(* Logix 5000 project; controller Test vendor 1 type 14 code 92 rev 33.11; software revision 33.00; part 2 of 4 *)
(* tags used below, declared in another part *)
   WLS : Banner_WLS_v4;
   Port_Data : Banner_IOL_Port_v4;
   Port : INT;   // Port Number that device is plugged into.
   Type : SINT;   // 0 = WLS27, 1 = WLS15, 2 = WLF
   Local_Control : DINT;
   Command_Being_Processed : BOOL;
   Update_Archive : BOOL;
   Index_Write_Inprocess : DINT;
   Index_Write_Control : DINT;
   IndexR : DINT;   // Index keeping track of Reads in an array.
   S_Index : DINT;
   IndexW : DINT;   // Index keeping track of Writes in an array.
(* Banner_WLS_Param_v4, continued *)

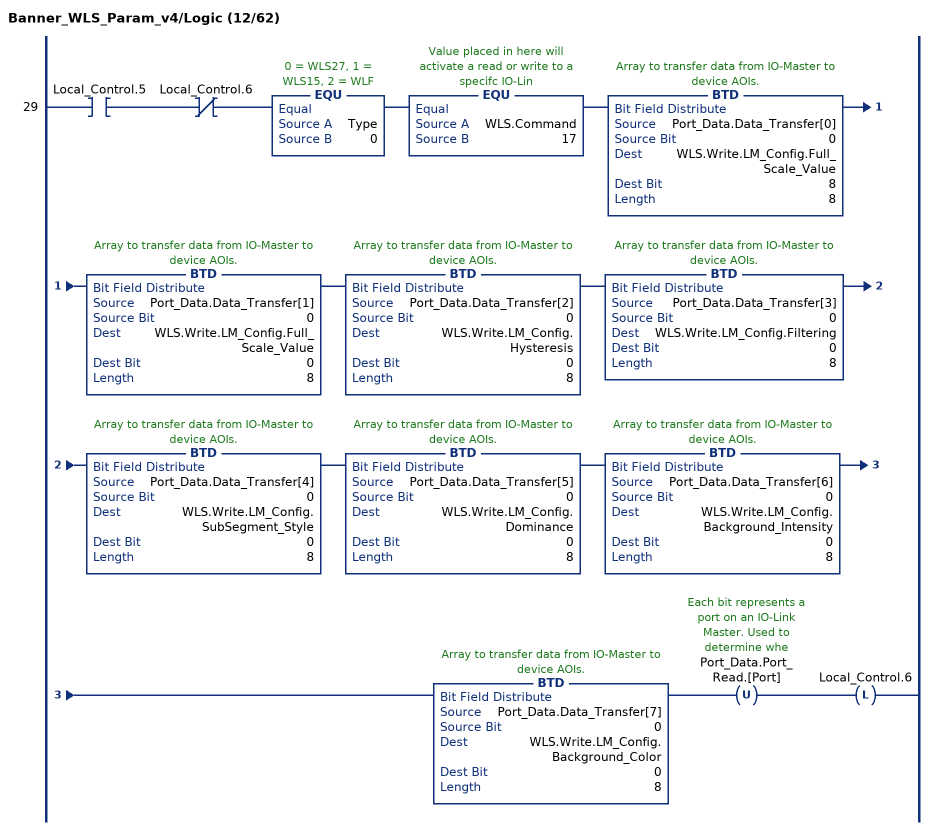
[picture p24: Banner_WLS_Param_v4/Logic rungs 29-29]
   29: XIC(Local_Control.5)XIO(Local_Control.6)EQU(Type,0)EQU(WLS.Command,17)BTD(Port_Data.Data_Transfer[0],0,WLS.Write.LM_Config.Full_Scale_Value,8,8)BTD(Port_Data.Data_Transfer[1],0,WLS.Write.LM_Config.Full_Scale_Value,0,8)BTD(Port_Data.Data_Transfer[2],0,WLS.Write.LM_Config.Hysteresis,0,8)BTD(Port_Data.Data_Transfer[3],0,WLS.Write.LM_Config.Filtering,0,8)BTD(Port_Data.Data_Transfer[4],0,WLS.Write.LM_Config.SubSegment_Style,0,8)BTD(Port_Data.Data_Transfer[5],0,WLS.Write.LM_Config.Dominance,0,8)BTD(Port_Data.Data_Transfer[6],0,WLS.Write.LM_Config.Background_Intensity,0,8)BTD(Port_Data.Data_Transfer[7],0,WLS.Write.LM_Config.Background_Color,0,8)OTU(Port_Data.Port_Read.[Port])OTL(Local_Control.6);
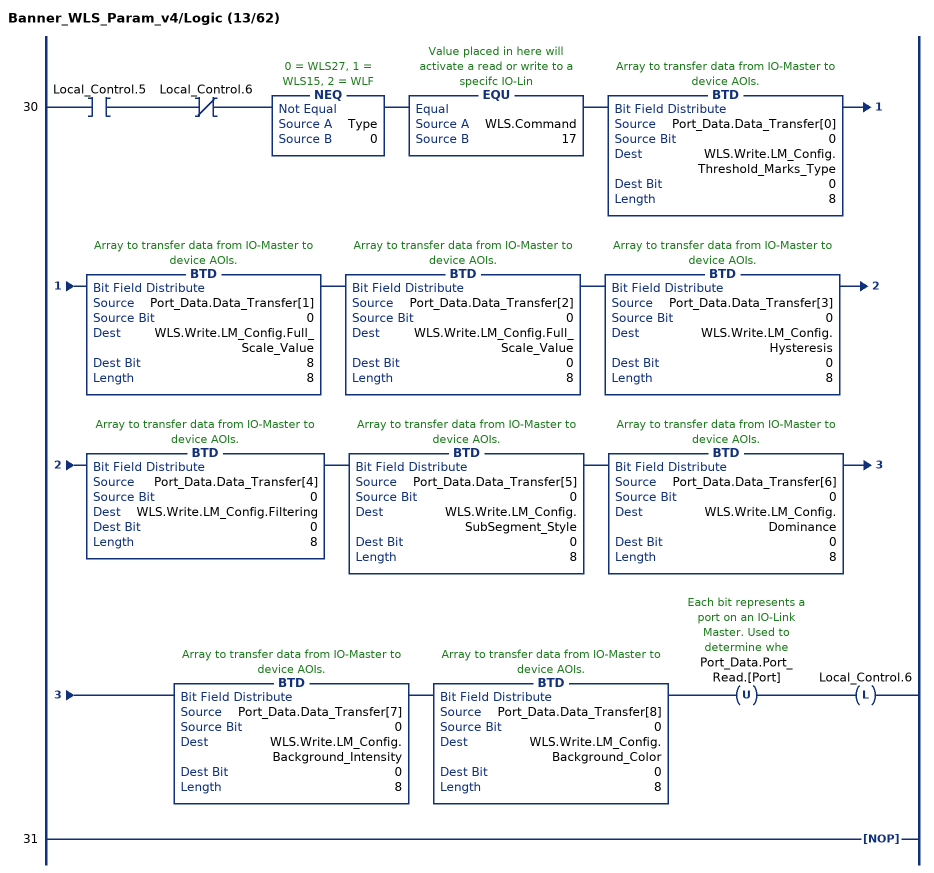
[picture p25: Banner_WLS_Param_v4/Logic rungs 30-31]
   30: XIC(Local_Control.5)XIO(Local_Control.6)NEQ(Type,0)EQU(WLS.Command,17)BTD(Port_Data.Data_Transfer[0],0,WLS.Write.LM_Config.Threshold_Marks_Type,0,8)BTD(Port_Data.Data_Transfer[1],0,WLS.Write.LM_Config.Full_Scale_Value,8,8)BTD(Port_Data.Data_Transfer[2],0,WLS.Write.LM_Config.Full_Scale_Value,0,8)BTD(Port_Data.Data_Transfer[3],0,WLS.Write.LM_Config.Hysteresis,0,8)BTD(Port_Data.Data_Transfer[4],0,WLS.Write.LM_Config.Filtering,0,8)BTD(Port_Data.Data_Transfer[5],0,WLS.Write.LM_Config.SubSegment_Style,0,8)BTD(Port_Data.Data_Transfer[6],0,WLS.Write.LM_Config.Dominance,0,8)BTD(Port_Data.Data_Transfer[7],0,WLS.Write.LM_Config.Background_Intensity,0,8)BTD(Port_Data.Data_Transfer[8],0,WLS.Write.LM_Config.Background_Color,0,8)OTU(Port_Data.Port_Read.[Port])OTL(Local_Control.6);
   31: NOP();
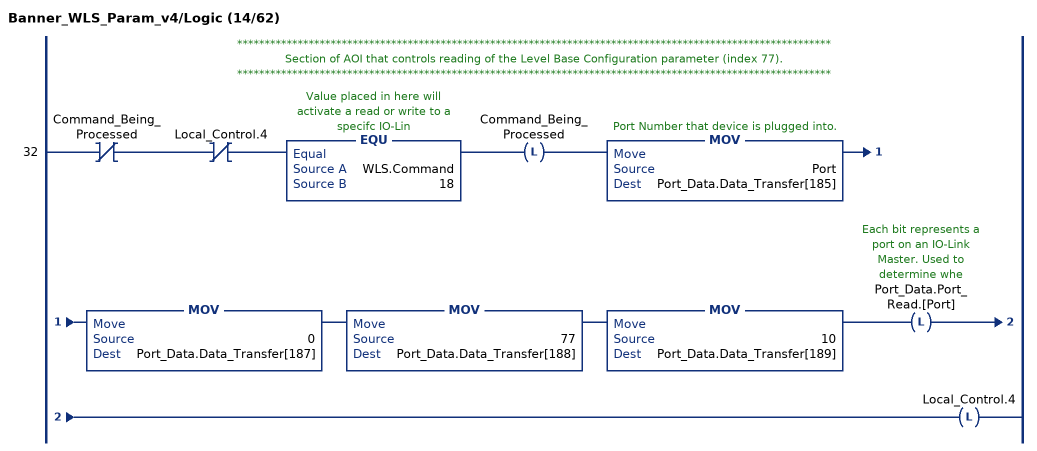
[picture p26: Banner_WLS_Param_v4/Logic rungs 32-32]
   // ************************************************************************************************************
   // Section of AOI that controls reading of the Level Base Configuration parameter (index 77).
   // ************************************************************************************************************
   32: XIO(Command_Being_Processed)XIO(Local_Control.4)EQU(WLS.Command,18)OTL(Command_Being_Processed)MOV(Port,Port_Data.Data_Transfer[185])MOV(0,Port_Data.Data_Transfer[187])MOV(77,Port_Data.Data_Transfer[188])MOV(10,Port_Data.Data_Transfer[189])OTL(Port_Data.Port_Read.[Port])OTL(Local_Control.4);
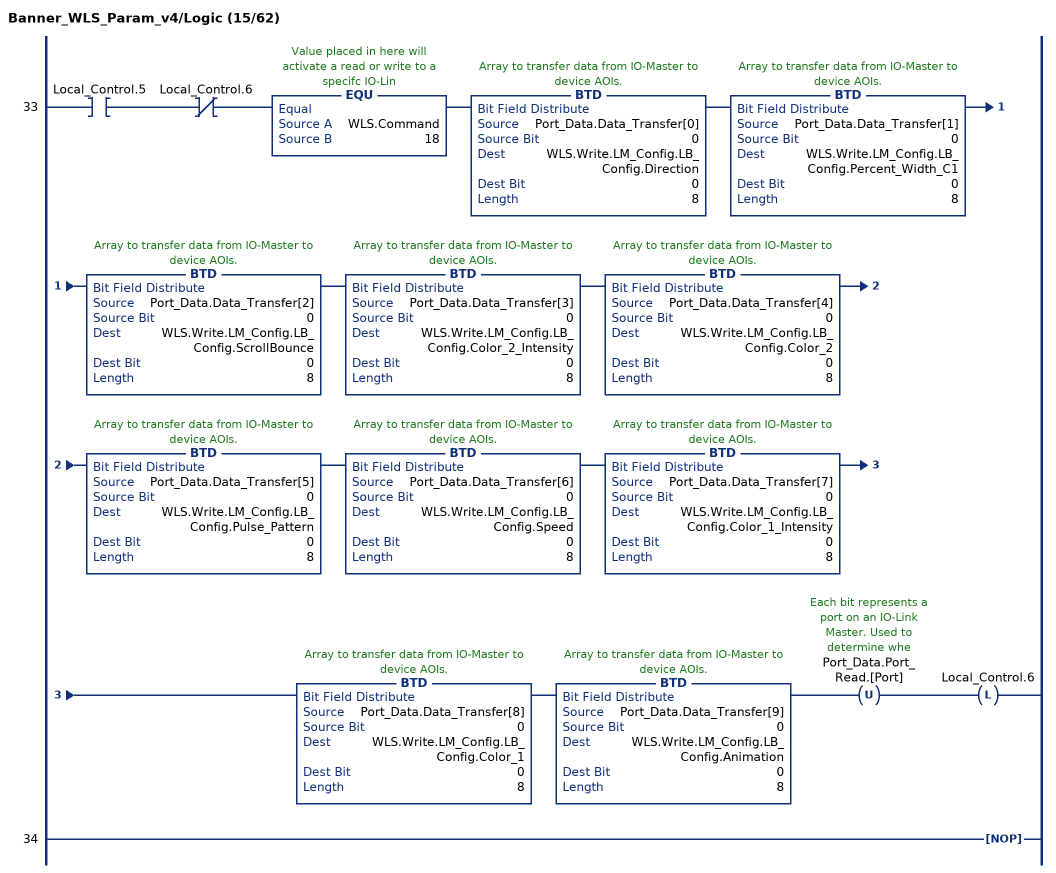
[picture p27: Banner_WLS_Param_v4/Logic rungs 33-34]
   33: XIC(Local_Control.5)XIO(Local_Control.6)EQU(WLS.Command,18)BTD(Port_Data.Data_Transfer[0],0,WLS.Write.LM_Config.LB_Config.Direction,0,8)BTD(Port_Data.Data_Transfer[1],0,WLS.Write.LM_Config.LB_Config.Percent_Width_C1,0,8)BTD(Port_Data.Data_Transfer[2],0,WLS.Write.LM_Config.LB_Config.ScrollBounce,0,8)BTD(Port_Data.Data_Transfer[3],0,WLS.Write.LM_Config.LB_Config.Color_2_Intensity,0,8)BTD(Port_Data.Data_Transfer[4],0,WLS.Write.LM_Config.LB_Config.Color_2,0,8)BTD(Port_Data.Data_Transfer[5],0,WLS.Write.LM_Config.LB_Config.Pulse_Pattern,0,8)BTD(Port_Data.Data_Transfer[6],0,WLS.Write.LM_Config.LB_Config.Speed,0,8)BTD(Port_Data.Data_Transfer[7],0,WLS.Write.LM_Config.LB_Config.Color_1_Intensity,0,8)BTD(Port_Data.Data_Transfer[8],0,WLS.Write.LM_Config.LB_Config.Color_1,0,8)BTD(Port_Data.Data_Transfer[9],0,WLS.Write.LM_Config.LB_Config.Animation,0,8)OTU(Port_Data.Port_Read.[Port])OTL(Local_Control.6);
   34: NOP();
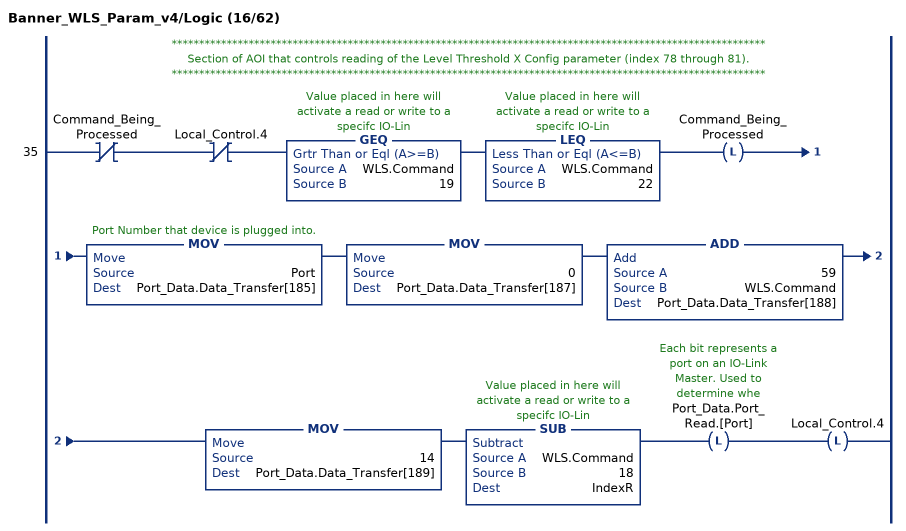
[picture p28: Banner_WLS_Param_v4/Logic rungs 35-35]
   // ************************************************************************************************************
   // Section of AOI that controls reading of the Level Threshold X Config parameter (index 78 through 81).
   // ************************************************************************************************************
   35: XIO(Command_Being_Processed)XIO(Local_Control.4)GEQ(WLS.Command,19)LEQ(WLS.Command,22)OTL(Command_Being_Processed)MOV(Port,Port_Data.Data_Transfer[185])MOV(0,Port_Data.Data_Transfer[187])ADD(59,WLS.Command,Port_Data.Data_Transfer[188])MOV(14,Port_Data.Data_Transfer[189])SUB(WLS.Command,18,IndexR)OTL(Port_Data.Port_Read.[Port])OTL(Local_Control.4);
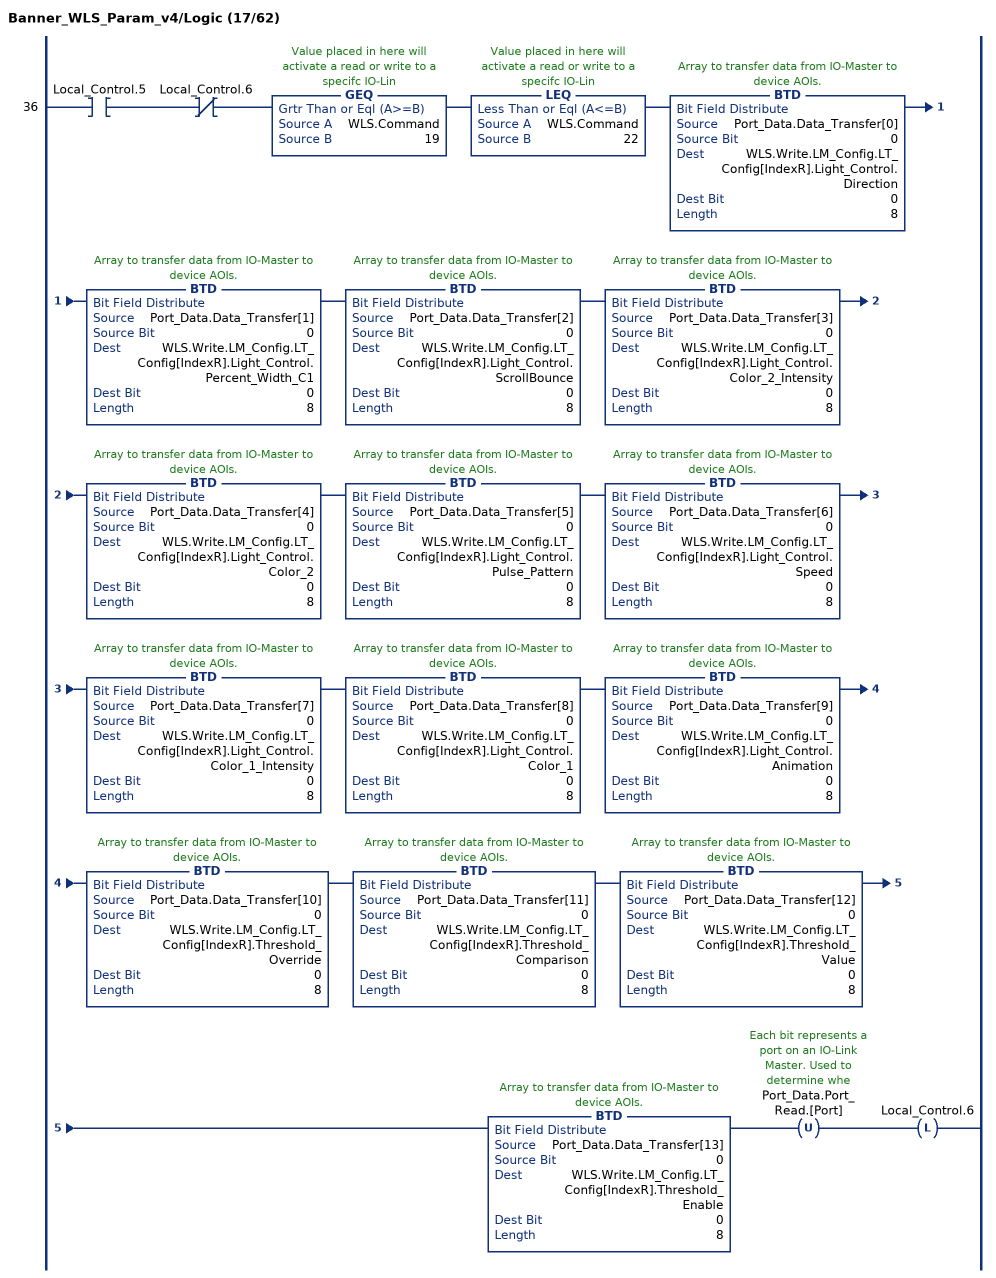
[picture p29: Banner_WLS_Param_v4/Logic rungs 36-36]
   36: XIC(Local_Control.5)XIO(Local_Control.6)GEQ(WLS.Command,19)LEQ(WLS.Command,22)BTD(Port_Data.Data_Transfer[0],0,WLS.Write.LM_Config.LT_Config[IndexR].Light_Control.Direction,0,8)BTD(Port_Data.Data_Transfer[1],0,WLS.Write.LM_Config.LT_Config[IndexR].Light_Control.Percent_Width_C1,0,8)BTD(Port_Data.Data_Transfer[2],0,WLS.Write.LM_Config.LT_Config[IndexR].Light_Control.ScrollBounce,0,8)BTD(Port_Data.Data_Transfer[3],0,WLS.Write.LM_Config.LT_Config[IndexR].Light_Control.Color_2_Intensity,0,8)BTD(Port_Data.Data_Transfer[4],0,WLS.Write.LM_Config.LT_Config[IndexR].Light_Control.Color_2,0,8)BTD(Port_Data.Data_Transfer[5],0,WLS.Write.LM_Config.LT_Config[IndexR].Light_Control.Pulse_Pattern,0,8)BTD(Port_Data.Data_Transfer[6],0,WLS.Write.LM_Config.LT_Config[IndexR].Light_Control.Speed,0,8)BTD(Port_Data.Data_Transfer[7],0,WLS.Write.LM_Config.LT_Config[IndexR].Light_Control.Color_1_Intensity,0,8)BTD(Port_Data.Data_Transfer[8],0,WLS.Write.LM_Config.LT_Config[IndexR].Light_Control.Color_1,0,8)BTD(Port_Data.Data_Transfer[9],0,WLS.Write.LM_Config.LT_Config[IndexR].Light_Control.Animation,0,8)BTD(Port_Data.Data_Transfer[10],0,WLS.Write.LM_Config.LT_Config[IndexR].Threshold_Override,0,8)BTD(Port_Data.Data_Transfer[11],0,WLS.Write.LM_Config.LT_Config[IndexR].Threshold_Comparison,0,8)BTD(Port_Data.Data_Transfer[12],0,WLS.Write.LM_Config.LT_Config[IndexR].Threshold_Value,0,8)BTD(Port_Data.Data_Transfer[13],0,WLS.Write.LM_Config.LT_Config[IndexR].Threshold_Enable,0,8)OTU(Port_Data.Port_Read.[Port])OTL(Local_Control.6);
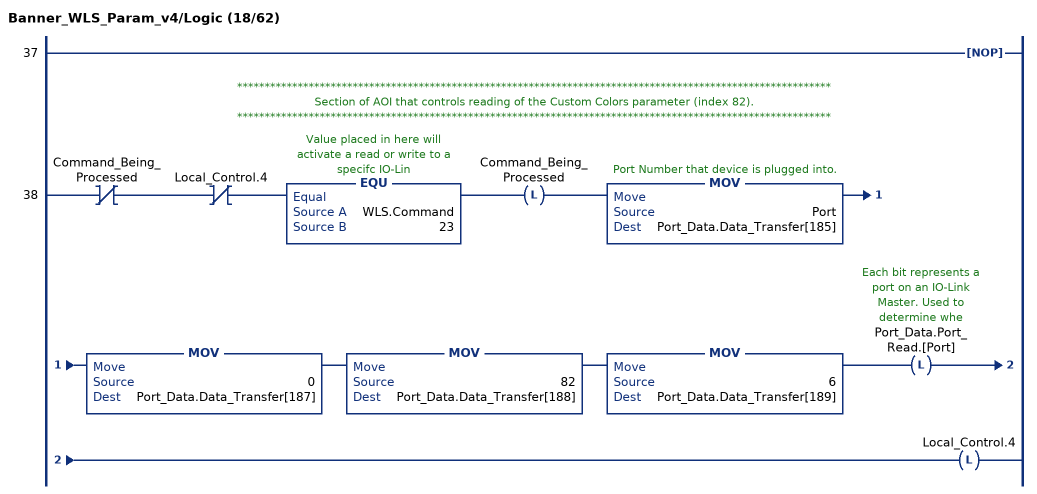
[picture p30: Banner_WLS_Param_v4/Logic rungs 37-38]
   37: NOP();
   // ************************************************************************************************************
   // Section of AOI that controls reading of the Custom Colors parameter (index 82).
   // ************************************************************************************************************
   38: XIO(Command_Being_Processed)XIO(Local_Control.4)EQU(WLS.Command,23)OTL(Command_Being_Processed)MOV(Port,Port_Data.Data_Transfer[185])MOV(0,Port_Data.Data_Transfer[187])MOV(82,Port_Data.Data_Transfer[188])MOV(6,Port_Data.Data_Transfer[189])OTL(Port_Data.Port_Read.[Port])OTL(Local_Control.4);
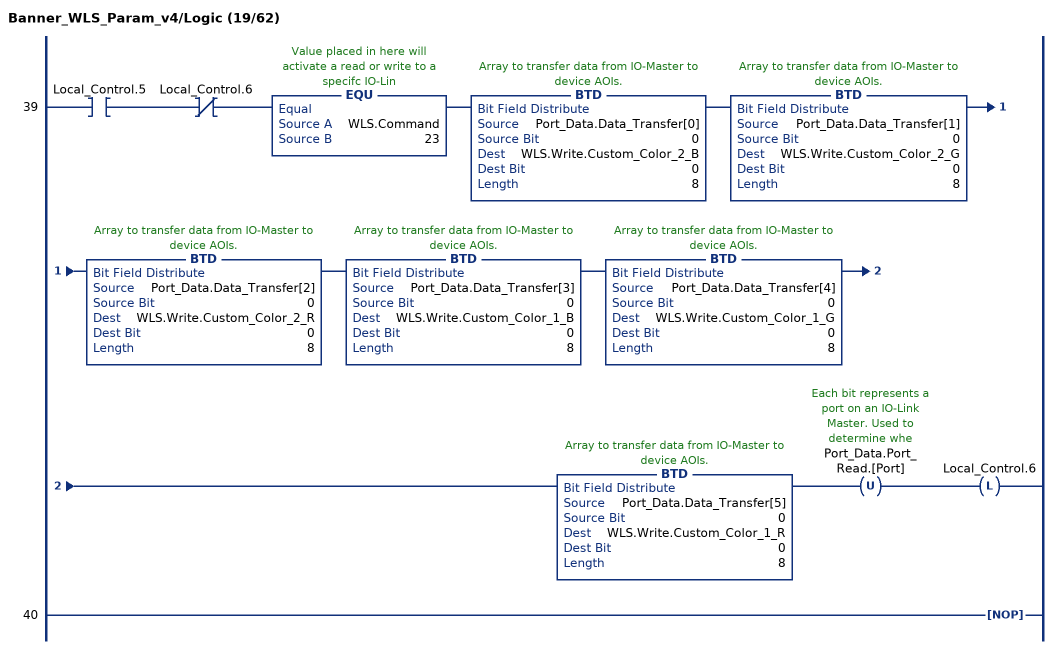
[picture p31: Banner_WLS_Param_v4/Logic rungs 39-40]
   39: XIC(Local_Control.5)XIO(Local_Control.6)EQU(WLS.Command,23)BTD(Port_Data.Data_Transfer[0],0,WLS.Write.Custom_Color_2_B,0,8)BTD(Port_Data.Data_Transfer[1],0,WLS.Write.Custom_Color_2_G,0,8)BTD(Port_Data.Data_Transfer[2],0,WLS.Write.Custom_Color_2_R,0,8)BTD(Port_Data.Data_Transfer[3],0,WLS.Write.Custom_Color_1_B,0,8)BTD(Port_Data.Data_Transfer[4],0,WLS.Write.Custom_Color_1_G,0,8)BTD(Port_Data.Data_Transfer[5],0,WLS.Write.Custom_Color_1_R,0,8)OTU(Port_Data.Port_Read.[Port])OTL(Local_Control.6);
   40: NOP();
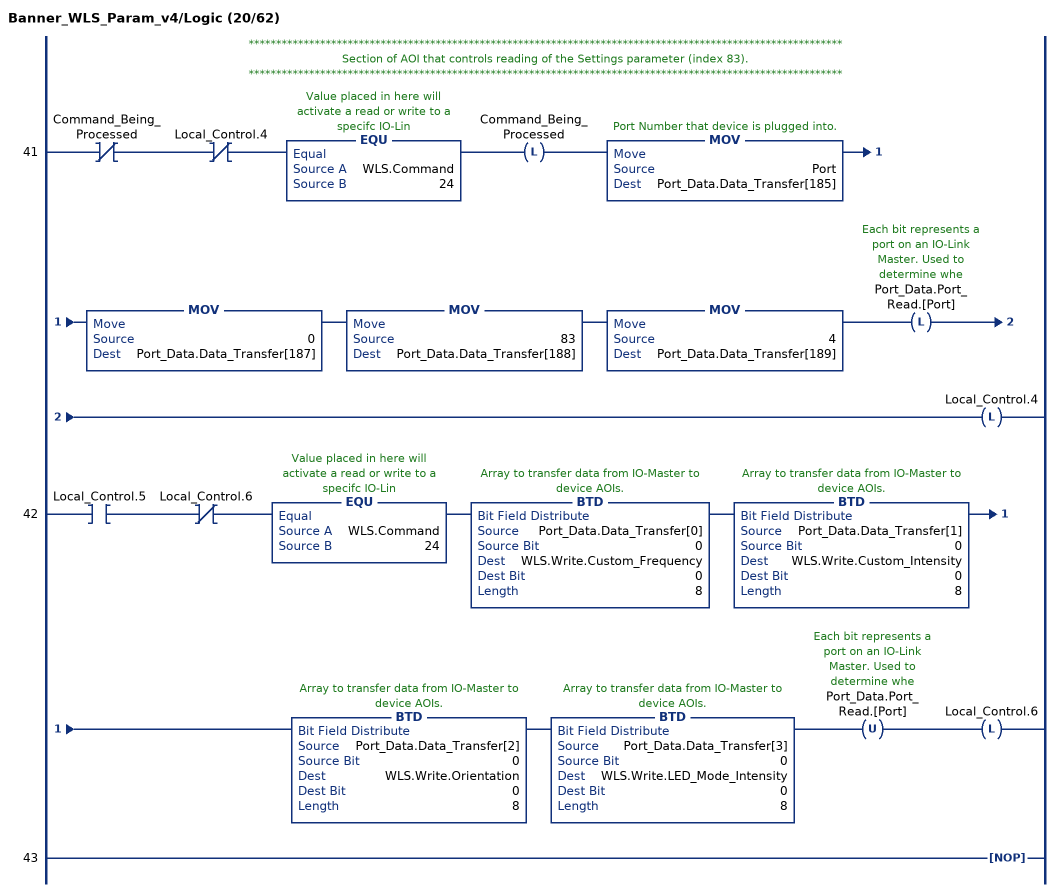
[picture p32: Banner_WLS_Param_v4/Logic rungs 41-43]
   // ************************************************************************************************************
   // Section of AOI that controls reading of the Settings parameter (index 83).
   // ************************************************************************************************************
   41: XIO(Command_Being_Processed)XIO(Local_Control.4)EQU(WLS.Command,24)OTL(Command_Being_Processed)MOV(Port,Port_Data.Data_Transfer[185])MOV(0,Port_Data.Data_Transfer[187])MOV(83,Port_Data.Data_Transfer[188])MOV(4,Port_Data.Data_Transfer[189])OTL(Port_Data.Port_Read.[Port])OTL(Local_Control.4);
   42: XIC(Local_Control.5)XIO(Local_Control.6)EQU(WLS.Command,24)BTD(Port_Data.Data_Transfer[0],0,WLS.Write.Custom_Frequency,0,8)BTD(Port_Data.Data_Transfer[1],0,WLS.Write.Custom_Intensity,0,8)BTD(Port_Data.Data_Transfer[2],0,WLS.Write.Orientation,0,8)BTD(Port_Data.Data_Transfer[3],0,WLS.Write.LED_Mode_Intensity,0,8)OTU(Port_Data.Port_Read.[Port])OTL(Local_Control.6);
   43: NOP();
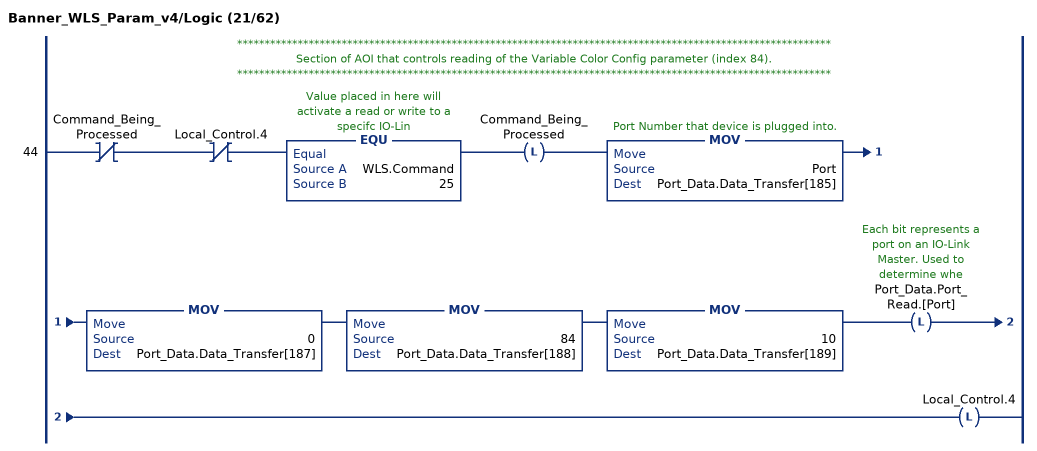
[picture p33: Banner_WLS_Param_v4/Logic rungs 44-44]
   // ************************************************************************************************************
   // Section of AOI that controls reading of the Variable Color Config parameter (index 84).
   // ************************************************************************************************************
   44: XIO(Command_Being_Processed)XIO(Local_Control.4)EQU(WLS.Command,25)OTL(Command_Being_Processed)MOV(Port,Port_Data.Data_Transfer[185])MOV(0,Port_Data.Data_Transfer[187])MOV(84,Port_Data.Data_Transfer[188])MOV(10,Port_Data.Data_Transfer[189])OTL(Port_Data.Port_Read.[Port])OTL(Local_Control.4);
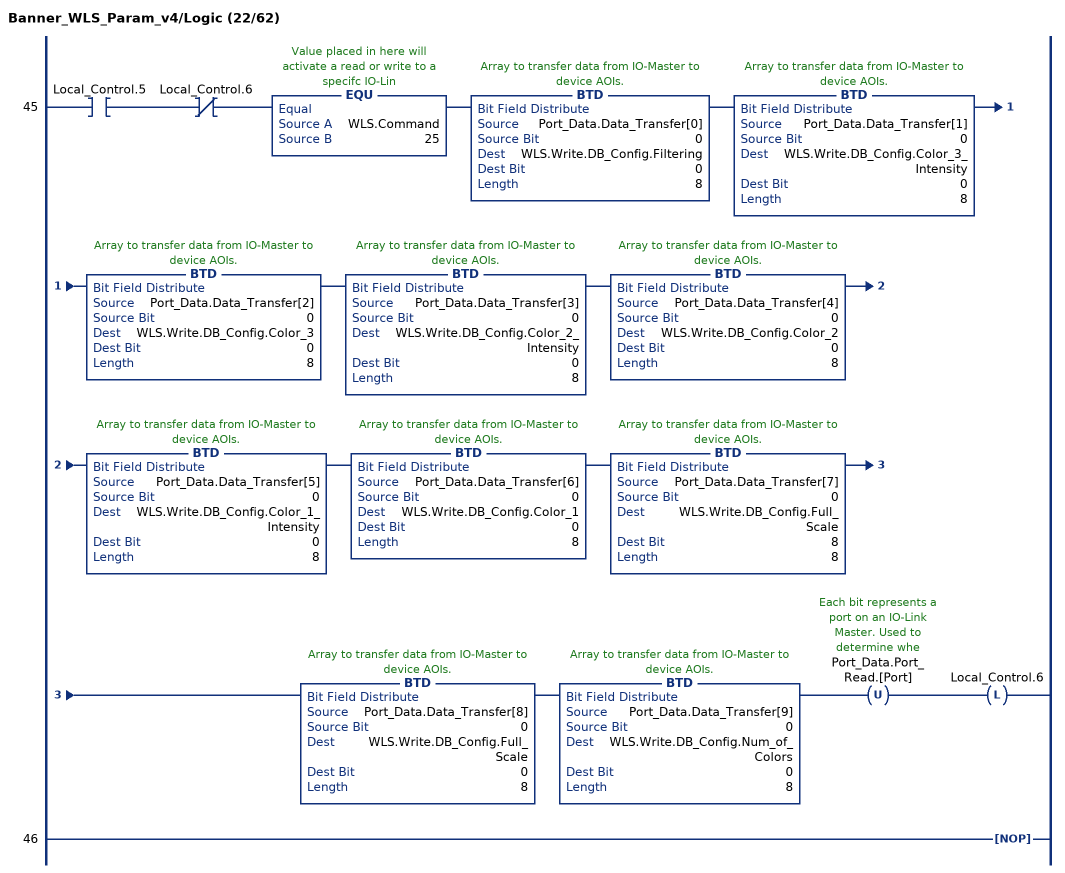
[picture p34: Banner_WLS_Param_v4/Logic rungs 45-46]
   45: XIC(Local_Control.5)XIO(Local_Control.6)EQU(WLS.Command,25)BTD(Port_Data.Data_Transfer[0],0,WLS.Write.DB_Config.Filtering,0,8)BTD(Port_Data.Data_Transfer[1],0,WLS.Write.DB_Config.Color_3_Intensity,0,8)BTD(Port_Data.Data_Transfer[2],0,WLS.Write.DB_Config.Color_3,0,8)BTD(Port_Data.Data_Transfer[3],0,WLS.Write.DB_Config.Color_2_Intensity,0,8)BTD(Port_Data.Data_Transfer[4],0,WLS.Write.DB_Config.Color_2,0,8)BTD(Port_Data.Data_Transfer[5],0,WLS.Write.DB_Config.Color_1_Intensity,0,8)BTD(Port_Data.Data_Transfer[6],0,WLS.Write.DB_Config.Color_1,0,8)BTD(Port_Data.Data_Transfer[7],0,WLS.Write.DB_Config.Full_Scale,8,8)BTD(Port_Data.Data_Transfer[8],0,WLS.Write.DB_Config.Full_Scale,0,8)BTD(Port_Data.Data_Transfer[9],0,WLS.Write.DB_Config.Num_of_Colors,0,8)OTU(Port_Data.Port_Read.[Port])OTL(Local_Control.6);
   46: NOP();
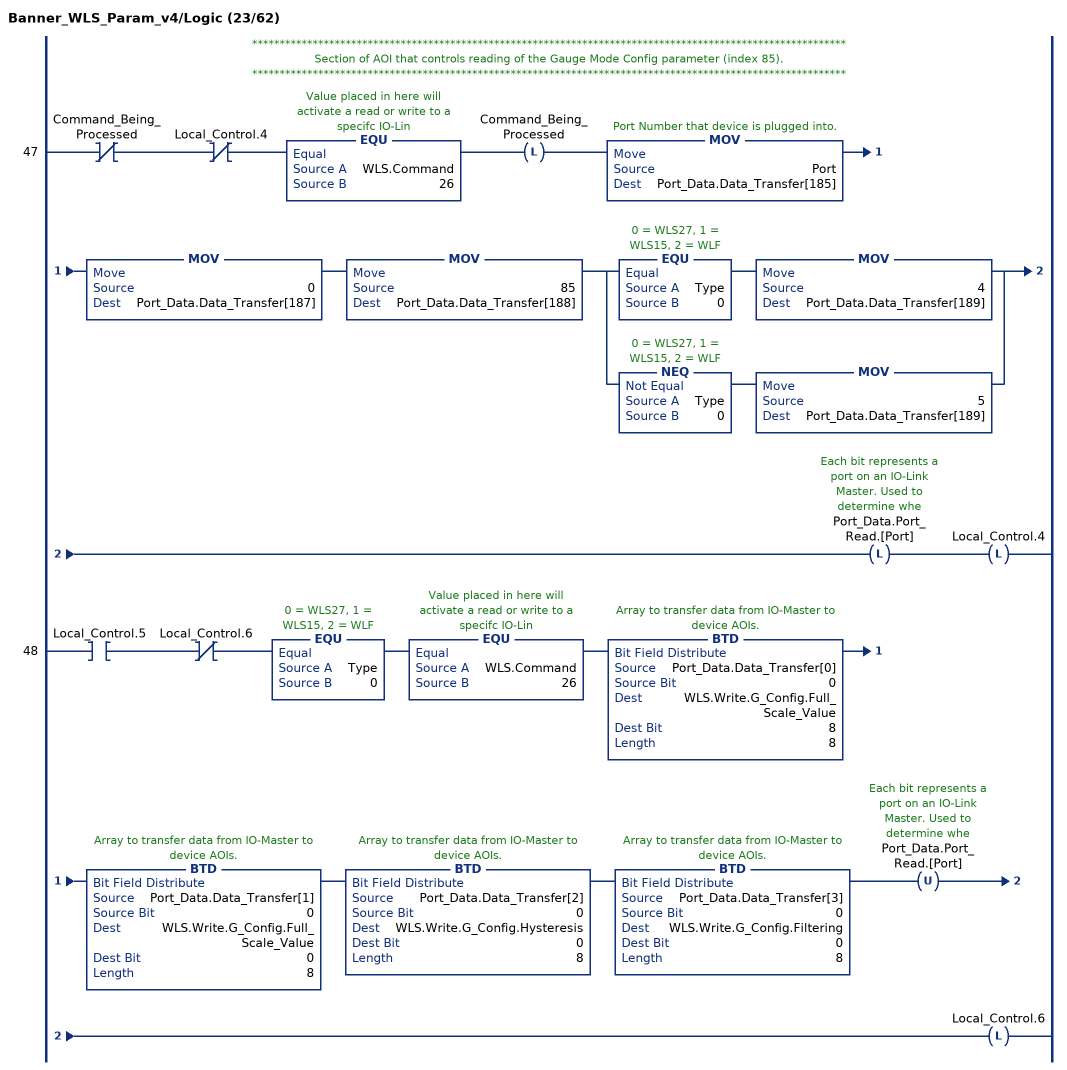
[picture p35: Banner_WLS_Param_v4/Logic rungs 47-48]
   // ************************************************************************************************************
   // Section of AOI that controls reading of the Gauge Mode Config parameter (index 85).
   // ************************************************************************************************************
   47: XIO(Command_Being_Processed)XIO(Local_Control.4)EQU(WLS.Command,26)OTL(Command_Being_Processed)MOV(Port,Port_Data.Data_Transfer[185])MOV(0,Port_Data.Data_Transfer[187])MOV(85,Port_Data.Data_Transfer[188])[EQU(Type,0) MOV(4,Port_Data.Data_Transfer[189]) ,NEQ(Type,0) MOV(5,Port_Data.Data_Transfer[189]) ]OTL(Port_Data.Port_Read.[Port])OTL(Local_Control.4);
   48: XIC(Local_Control.5)XIO(Local_Control.6)EQU(Type,0)EQU(WLS.Command,26)BTD(Port_Data.Data_Transfer[0],0,WLS.Write.G_Config.Full_Scale_Value,8,8)BTD(Port_Data.Data_Transfer[1],0,WLS.Write.G_Config.Full_Scale_Value,0,8)BTD(Port_Data.Data_Transfer[2],0,WLS.Write.G_Config.Hysteresis,0,8)BTD(Port_Data.Data_Transfer[3],0,WLS.Write.G_Config.Filtering,0,8)OTU(Port_Data.Port_Read.[Port])OTL(Local_Control.6);
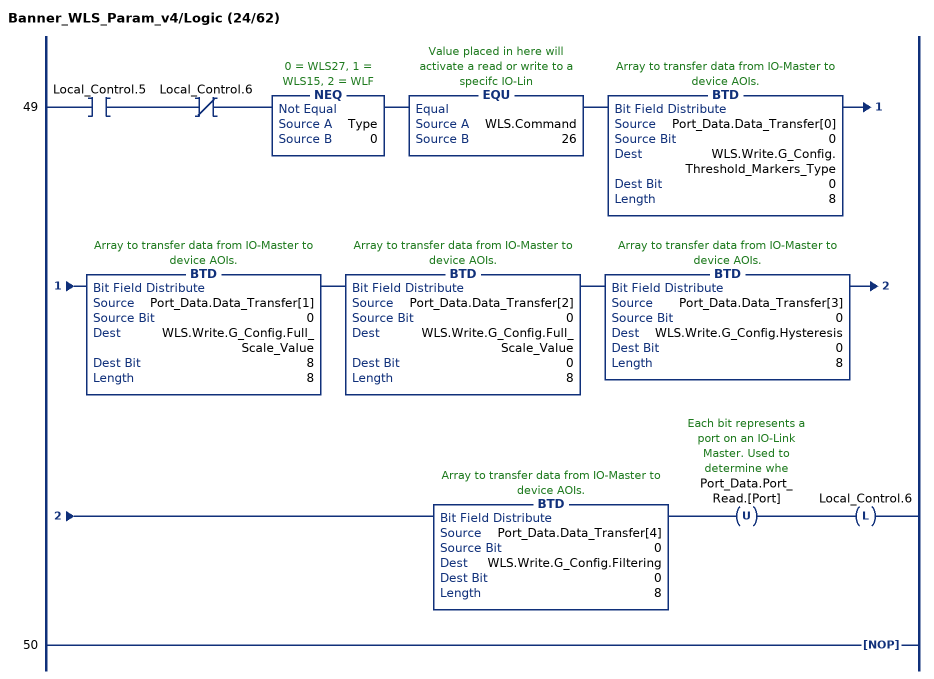
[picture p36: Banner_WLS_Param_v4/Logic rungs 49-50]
   49: XIC(Local_Control.5)XIO(Local_Control.6)NEQ(Type,0)EQU(WLS.Command,26)BTD(Port_Data.Data_Transfer[0],0,WLS.Write.G_Config.Threshold_Markers_Type,0,8)BTD(Port_Data.Data_Transfer[1],0,WLS.Write.G_Config.Full_Scale_Value,8,8)BTD(Port_Data.Data_Transfer[2],0,WLS.Write.G_Config.Full_Scale_Value,0,8)BTD(Port_Data.Data_Transfer[3],0,WLS.Write.G_Config.Hysteresis,0,8)BTD(Port_Data.Data_Transfer[4],0,WLS.Write.G_Config.Filtering,0,8)OTU(Port_Data.Port_Read.[Port])OTL(Local_Control.6);
   50: NOP();
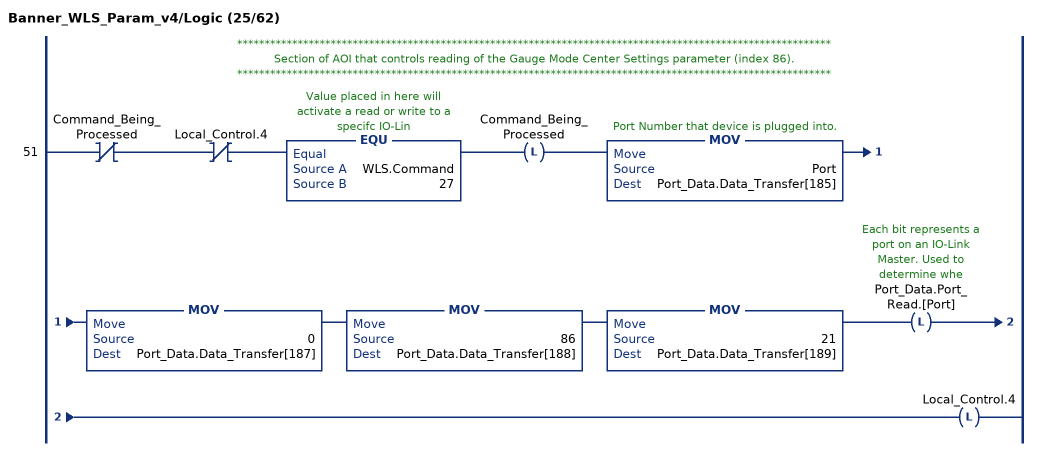
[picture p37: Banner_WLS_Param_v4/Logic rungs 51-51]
   // ************************************************************************************************************
   // Section of AOI that controls reading of the Gauge Mode Center Settings parameter (index 86).
   // ************************************************************************************************************
   51: XIO(Command_Being_Processed)XIO(Local_Control.4)EQU(WLS.Command,27)OTL(Command_Being_Processed)MOV(Port,Port_Data.Data_Transfer[185])MOV(0,Port_Data.Data_Transfer[187])MOV(86,Port_Data.Data_Transfer[188])MOV(21,Port_Data.Data_Transfer[189])OTL(Port_Data.Port_Read.[Port])OTL(Local_Control.4);
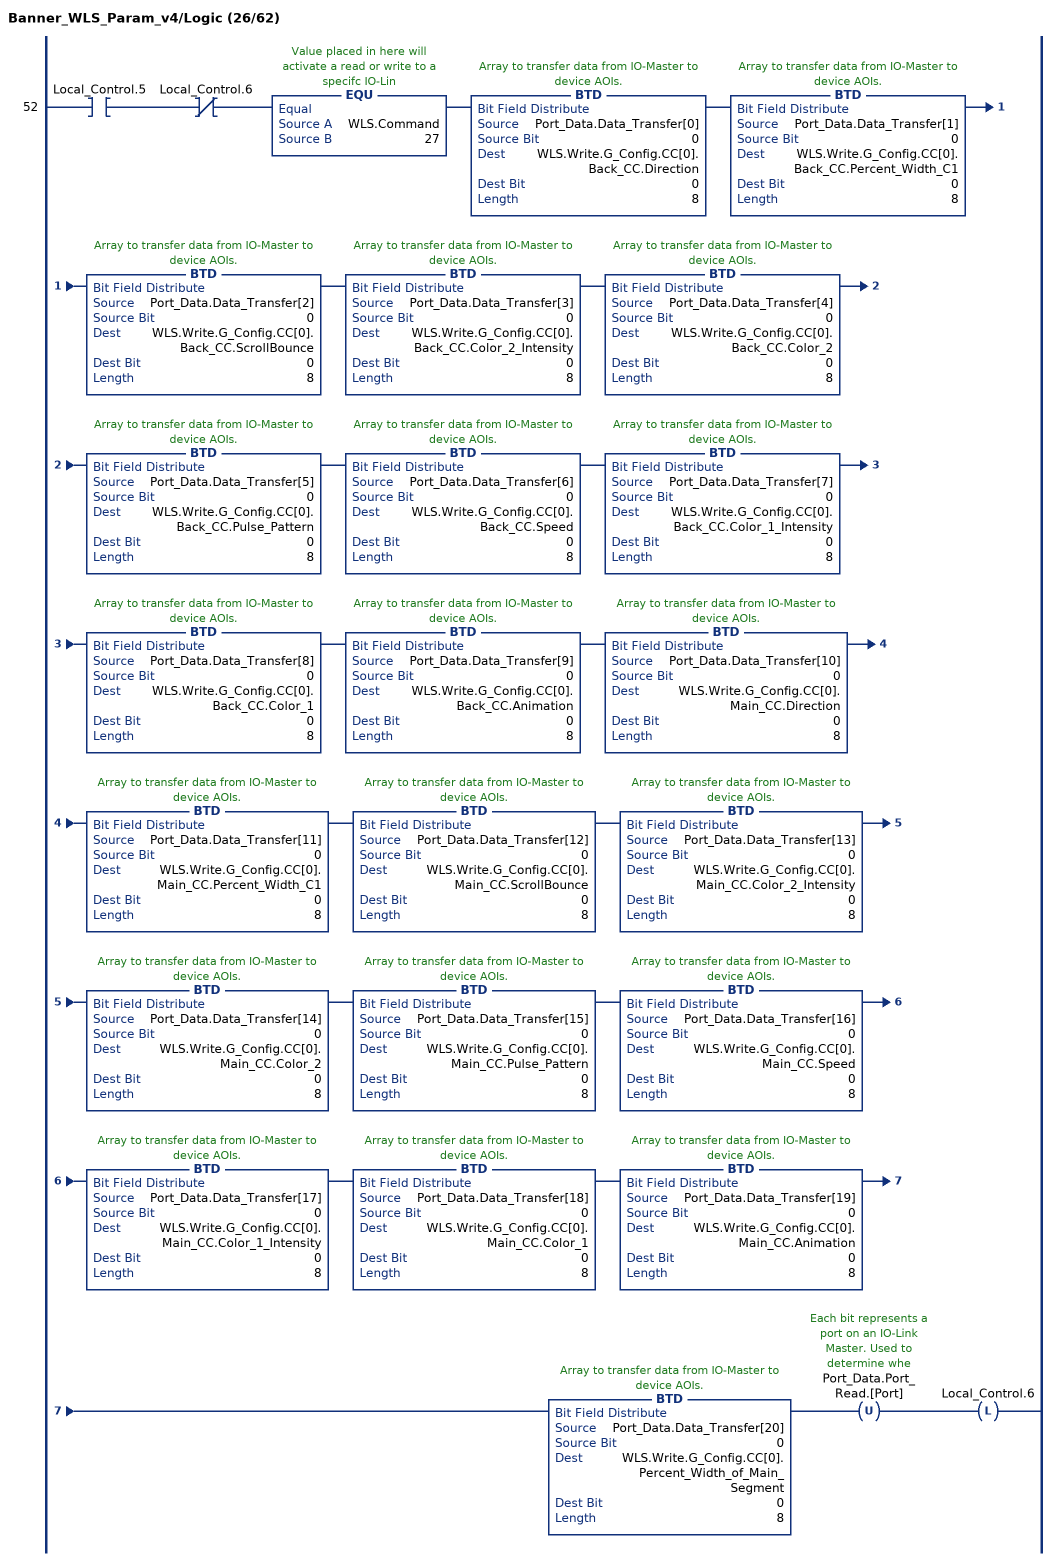
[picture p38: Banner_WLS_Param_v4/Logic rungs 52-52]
   52: XIC(Local_Control.5)XIO(Local_Control.6)EQU(WLS.Command,27)BTD(Port_Data.Data_Transfer[0],0,WLS.Write.G_Config.CC[0].Back_CC.Direction,0,8)BTD(Port_Data.Data_Transfer[1],0,WLS.Write.G_Config.CC[0].Back_CC.Percent_Width_C1,0,8)BTD(Port_Data.Data_Transfer[2],0,WLS.Write.G_Config.CC[0].Back_CC.ScrollBounce,0,8)BTD(Port_Data.Data_Transfer[3],0,WLS.Write.G_Config.CC[0].Back_CC.Color_2_Intensity,0,8)BTD(Port_Data.Data_Transfer[4],0,WLS.Write.G_Config.CC[0].Back_CC.Color_2,0,8)BTD(Port_Data.Data_Transfer[5],0,WLS.Write.G_Config.CC[0].Back_CC.Pulse_Pattern,0,8)BTD(Port_Data.Data_Transfer[6],0,WLS.Write.G_Config.CC[0].Back_CC.Speed,0,8)BTD(Port_Data.Data_Transfer[7],0,WLS.Write.G_Config.CC[0].Back_CC.Color_1_Intensity,0,8)BTD(Port_Data.Data_Transfer[8],0,WLS.Write.G_Config.CC[0].Back_CC.Color_1,0,8)BTD(Port_Data.Data_Transfer[9],0,WLS.Write.G_Config.CC[0].Back_CC.Animation,0,8)BTD(Port_Data.Data_Transfer[10],0,WLS.Write.G_Config.CC[0].Main_CC.Direction,0,8)BTD(Port_Data.Data_Transfer[11],0,WLS.Write.G_Config.CC[0].Main_CC.Percent_Width_C1,0,8)BTD(Port_Data.Data_Transfer[12],0,WLS.Write.G_Config.CC[0].Main_CC.ScrollBounce,0,8)BTD(Port_Data.Data_Transfer[13],0,WLS.Write.G_Config.CC[0].Main_CC.Color_2_Intensity,0,8)BTD(Port_Data.Data_Transfer[14],0,WLS.Write.G_Config.CC[0].Main_CC.Color_2,0,8)BTD(Port_Data.Data_Transfer[15],0,WLS.Write.G_Config.CC[0].Main_CC.Pulse_Pattern,0,8)BTD(Port_Data.Data_Transfer[16],0,WLS.Write.G_Config.CC[0].Main_CC.Speed,0,8)BTD(Port_Data.Data_Transfer[17],0,WLS.Write.G_Config.CC[0].Main_CC.Color_1_Intensity,0,8)BTD(Port_Data.Data_Transfer[18],0,WLS.Write.G_Config.CC[0].Main_CC.Color_1,0,8)BTD(Port_Data.Data_Transfer[19],0,WLS.Write.G_Config.CC[0].Main_CC.Animation,0,8)BTD(Port_Data.Data_Transfer[20],0,WLS.Write.G_Config.CC[0].Percent_Width_of_Main_Segment,0,8)OTU(Port_Data.Port_Read.[Port])OTL(Local_Control.6);
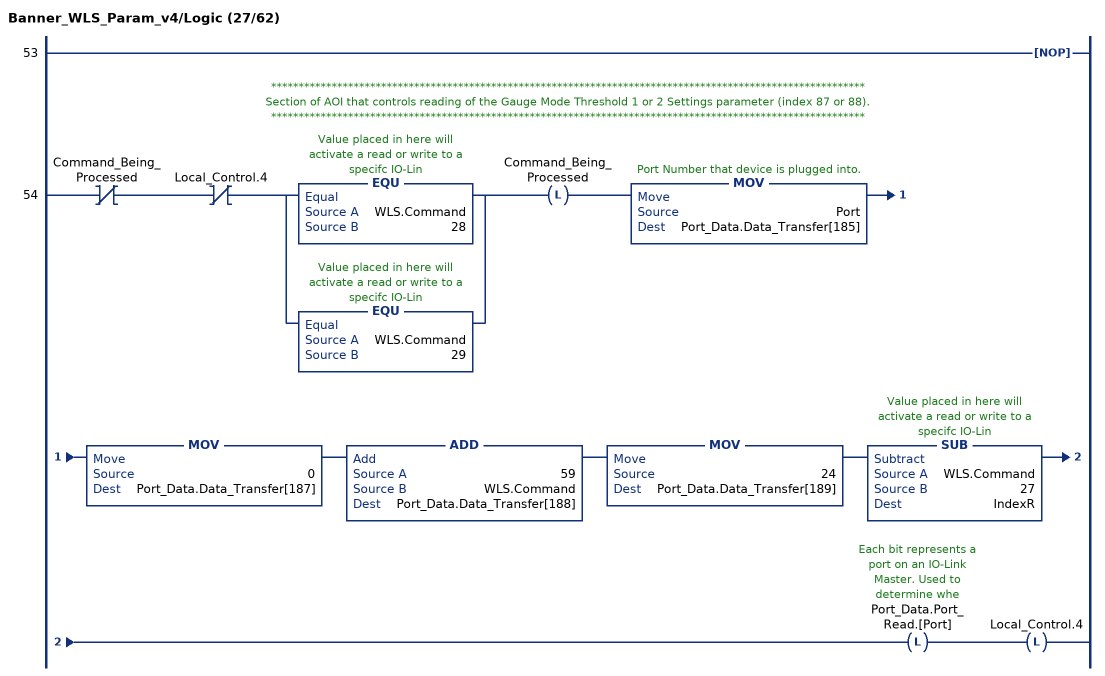
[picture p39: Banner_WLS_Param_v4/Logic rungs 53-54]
   53: NOP();
   // ************************************************************************************************************
   // Section of AOI that controls reading of the Gauge Mode Threshold 1 or 2 Settings parameter (index 87 or 88).
   // ************************************************************************************************************
   54: XIO(Command_Being_Processed)XIO(Local_Control.4)[EQU(WLS.Command,28) ,EQU(WLS.Command,29) ]OTL(Command_Being_Processed)MOV(Port,Port_Data.Data_Transfer[185])MOV(0,Port_Data.Data_Transfer[187])ADD(59,WLS.Command,Port_Data.Data_Transfer[188])MOV(24,Port_Data.Data_Transfer[189])SUB(WLS.Command,27,IndexR)OTL(Port_Data.Port_Read.[Port])OTL(Local_Control.4);
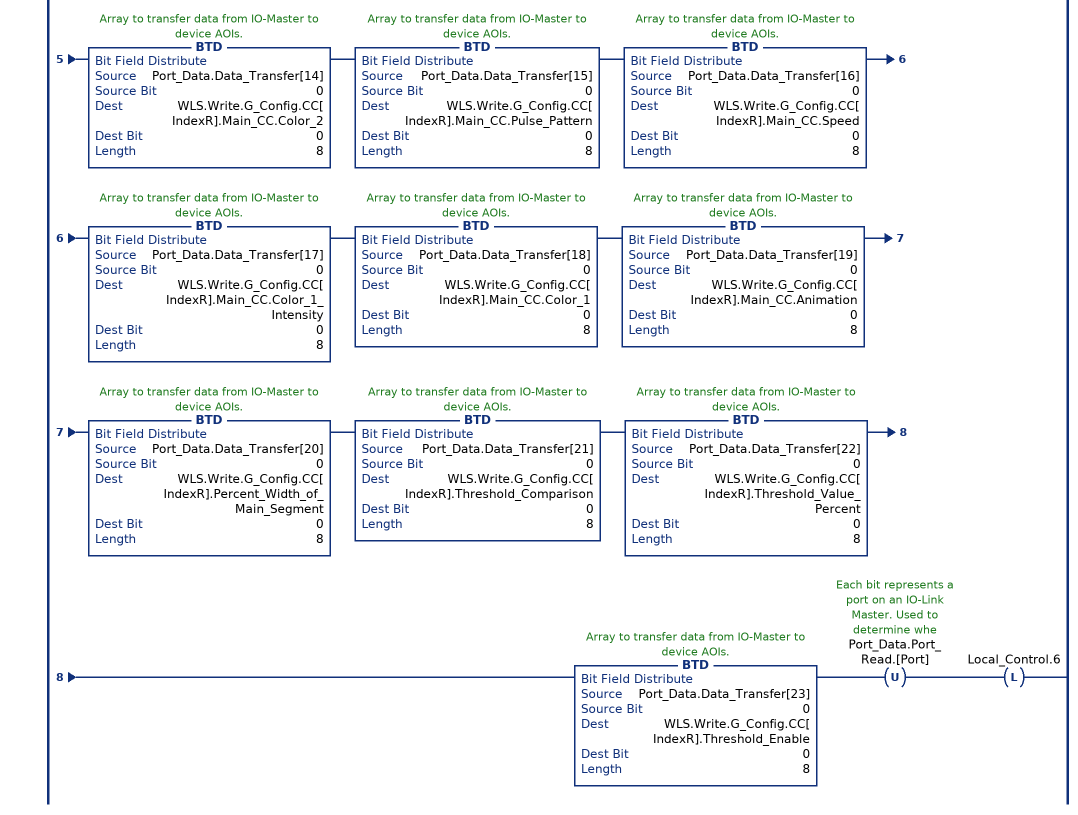
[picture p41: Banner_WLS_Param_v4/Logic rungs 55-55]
   55: XIC(Local_Control.5)XIO(Local_Control.6)[EQU(WLS.Command,28) ,EQU(WLS.Command,29) ]BTD(Port_Data.Data_Transfer[0],0,WLS.Write.G_Config.CC[IndexR].Back_CC.Direction,0,8)BTD(Port_Data.Data_Transfer[1],0,WLS.Write.G_Config.CC[IndexR].Back_CC.Percent_Width_C1,0,8)BTD(Port_Data.Data_Transfer[2],0,WLS.Write.G_Config.CC[IndexR].Back_CC.ScrollBounce,0,8)BTD(Port_Data.Data_Transfer[3],0,WLS.Write.G_Config.CC[IndexR].Back_CC.Color_2_Intensity,0,8)BTD(Port_Data.Data_Transfer[4],0,WLS.Write.G_Config.CC[IndexR].Back_CC.Color_2,0,8)BTD(Port_Data.Data_Transfer[5],0,WLS.Write.G_Config.CC[IndexR].Back_CC.Pulse_Pattern,0,8)BTD(Port_Data.Data_Transfer[6],0,WLS.Write.G_Config.CC[IndexR].Back_CC.Speed,0,8)BTD(Port_Data.Data_Transfer[7],0,WLS.Write.G_Config.CC[IndexR].Back_CC.Color_1_Intensity,0,8)BTD(Port_Data.Data_Transfer[8],0,WLS.Write.G_Config.CC[IndexR].Back_CC.Color_1,0,8)BTD(Port_Data.Data_Transfer[9],0,WLS.Write.G_Config.CC[IndexR].Back_CC.Animation,0,8)BTD(Port_Data.Data_Transfer[10],0,WLS.Write.G_Config.CC[IndexR].Main_CC.Direction,0,8)BTD(Port_Data.Data_Transfer[11],0,WLS.Write.G_Config.CC[IndexR].Main_CC.Percent_Width_C1,0,8)BTD(Port_Data.Data_Transfer[12],0,WLS.Write.G_Config.CC[IndexR].Main_CC.ScrollBounce,0,8)BTD(Port_Data.Data_Transfer[13],0,WLS.Write.G_Config.CC[IndexR].Main_CC.Color_2_Intensity,0,8)BTD(Port_Data.Data_Transfer[14],0,WLS.Write.G_Config.CC[IndexR].Main_CC.Color_2,0,8)BTD(Port_Data.Data_Transfer[15],0,WLS.Write.G_Config.CC[IndexR].Main_CC.Pulse_Pattern,0,8)BTD(Port_Data.Data_Transfer[16],0,WLS.Write.G_Config.CC[IndexR].Main_CC.Speed,0,8)BTD(Port_Data.Data_Transfer[17],0,WLS.Write.G_Config.CC[IndexR].Main_CC.Color_1_Intensity,0,8)BTD(Port_Data.Data_Transfer[18],0,WLS.Write.G_Config.CC[IndexR].Main_CC.Color_1,0,8)BTD(Port_Data.Data_Transfer[19],0,WLS.Write.G_Config.CC[IndexR].Main_CC.Animation,0,8)BTD(Port_Data.Data_Transfer[20],0,WLS.Write.G_Config.CC[IndexR].Percent_Width_of_Main_Segment,0,8)BTD(Port_Data.Data_Transfer[21],0,WLS.Write.G_Config.CC[IndexR].Threshold_Comparison,0,8)BTD(Port_Data.Data_Transfer[22],0,WLS.Write.G_Config.CC[IndexR].Threshold_Value_Percent,0,8)BTD(Port_Data.Data_Transfer[23],0,WLS.Write.G_Config.CC[IndexR].Threshold_Enable,0,8)OTU(Port_Data.Port_Read.[Port])OTL(Local_Control.6);
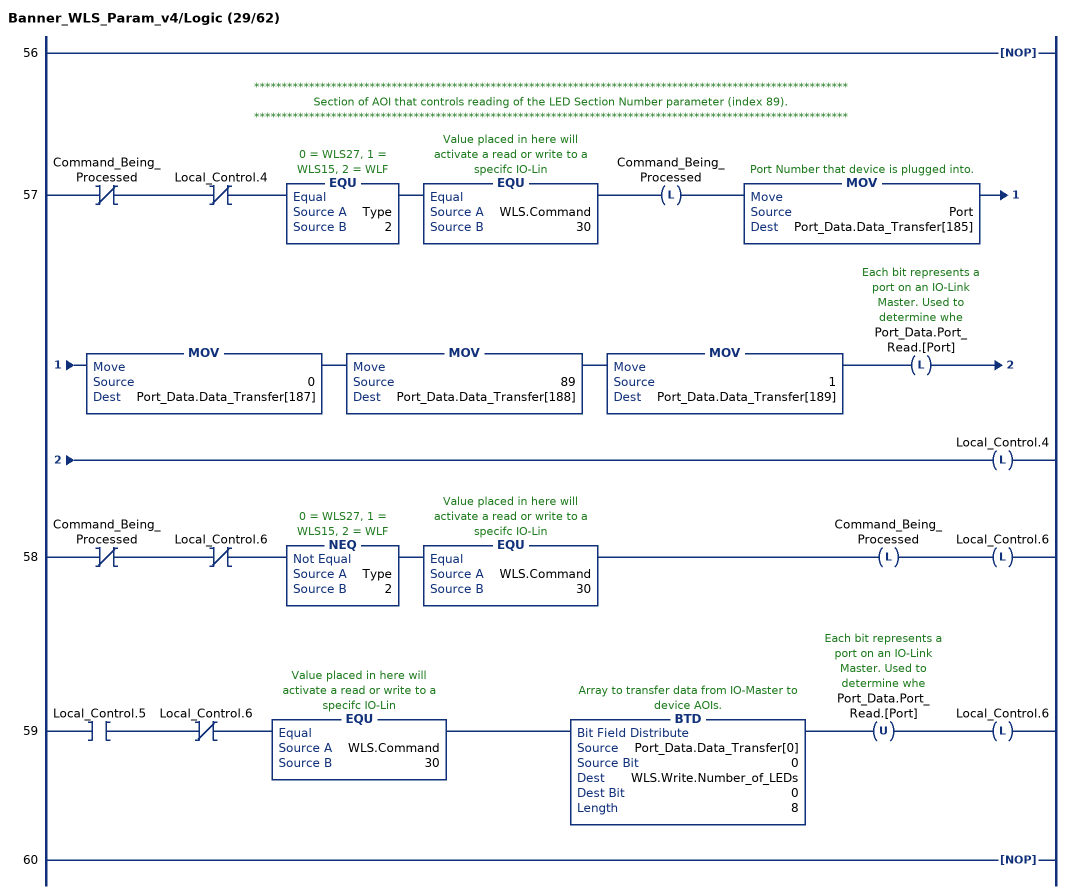
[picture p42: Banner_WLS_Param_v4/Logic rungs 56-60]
   56: NOP();
   // ************************************************************************************************************
   // Section of AOI that controls reading of the LED Section Number parameter (index 89).
   // ************************************************************************************************************
   57: XIO(Command_Being_Processed)XIO(Local_Control.4)EQU(Type,2)EQU(WLS.Command,30)OTL(Command_Being_Processed)MOV(Port,Port_Data.Data_Transfer[185])MOV(0,Port_Data.Data_Transfer[187])MOV(89,Port_Data.Data_Transfer[188])MOV(1,Port_Data.Data_Transfer[189])OTL(Port_Data.Port_Read.[Port])OTL(Local_Control.4);
   58: XIO(Command_Being_Processed)XIO(Local_Control.6)NEQ(Type,2)EQU(WLS.Command,30)OTL(Command_Being_Processed)OTL(Local_Control.6);
   59: XIC(Local_Control.5)XIO(Local_Control.6)EQU(WLS.Command,30)BTD(Port_Data.Data_Transfer[0],0,WLS.Write.Number_of_LEDs,0,8)OTU(Port_Data.Port_Read.[Port])OTL(Local_Control.6);
   60: NOP();
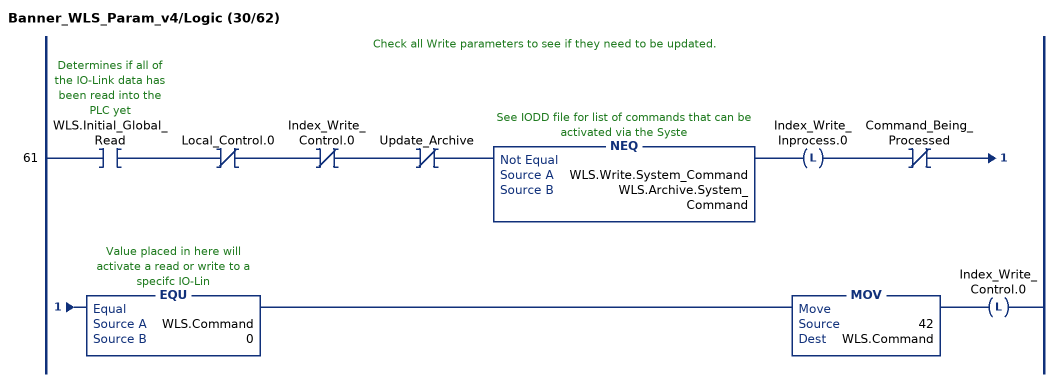
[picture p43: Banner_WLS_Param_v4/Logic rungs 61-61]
   // Check all Write parameters to see if they need to be updated.
   61: XIC(WLS.Initial_Global_Read)XIO(Local_Control.0)XIO(Index_Write_Control.0)XIO(Update_Archive)NEQ(WLS.Write.System_Command,WLS.Archive.System_Command)OTL(Index_Write_Inprocess.0)XIO(Command_Being_Processed)EQU(WLS.Command,0)MOV(42,WLS.Command)OTL(Index_Write_Control.0);
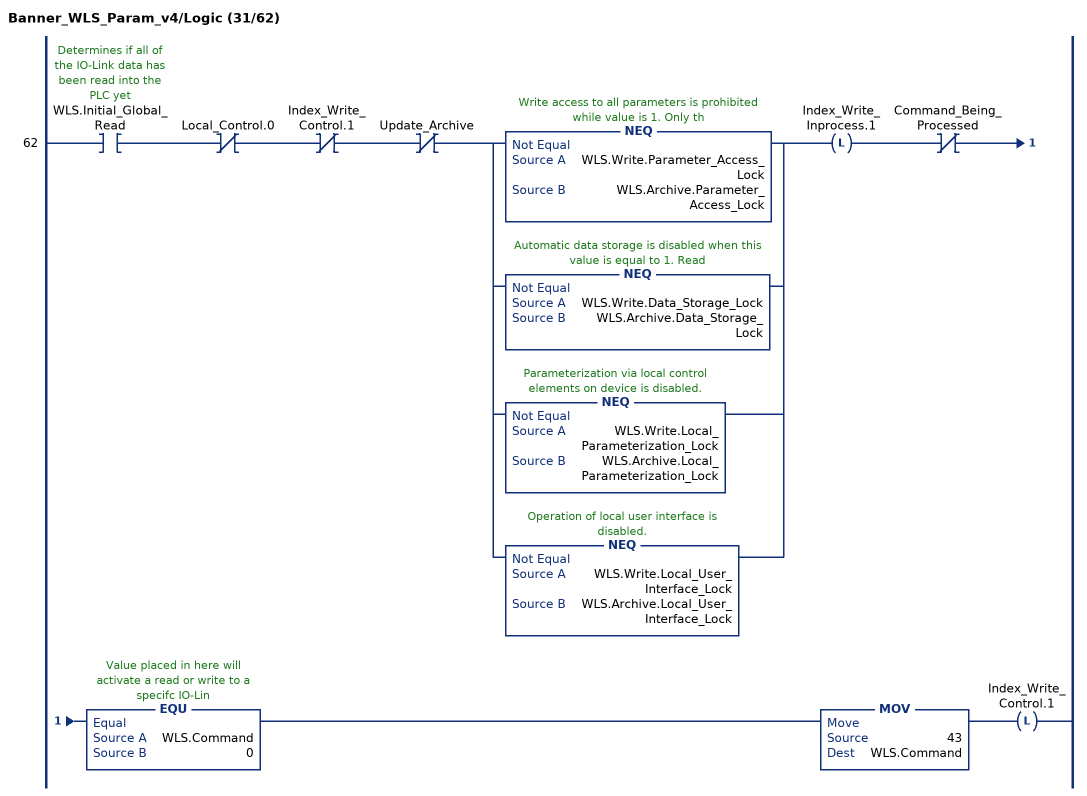
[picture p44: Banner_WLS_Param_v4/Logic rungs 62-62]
   62: XIC(WLS.Initial_Global_Read)XIO(Local_Control.0)XIO(Index_Write_Control.1)XIO(Update_Archive)[NEQ(WLS.Write.Parameter_Access_Lock,WLS.Archive.Parameter_Access_Lock) ,NEQ(WLS.Write.Data_Storage_Lock,WLS.Archive.Data_Storage_Lock) ,NEQ(WLS.Write.Local_Parameterization_Lock,WLS.Archive.Local_Parameterization_Lock) ,NEQ(WLS.Write.Local_User_Interface_Lock,WLS.Archive.Local_User_Interface_Lock) ]OTL(Index_Write_Inprocess.1)XIO(Command_Being_Processed)EQU(WLS.Command,0)MOV(43,WLS.Command)OTL(Index_Write_Control.1);
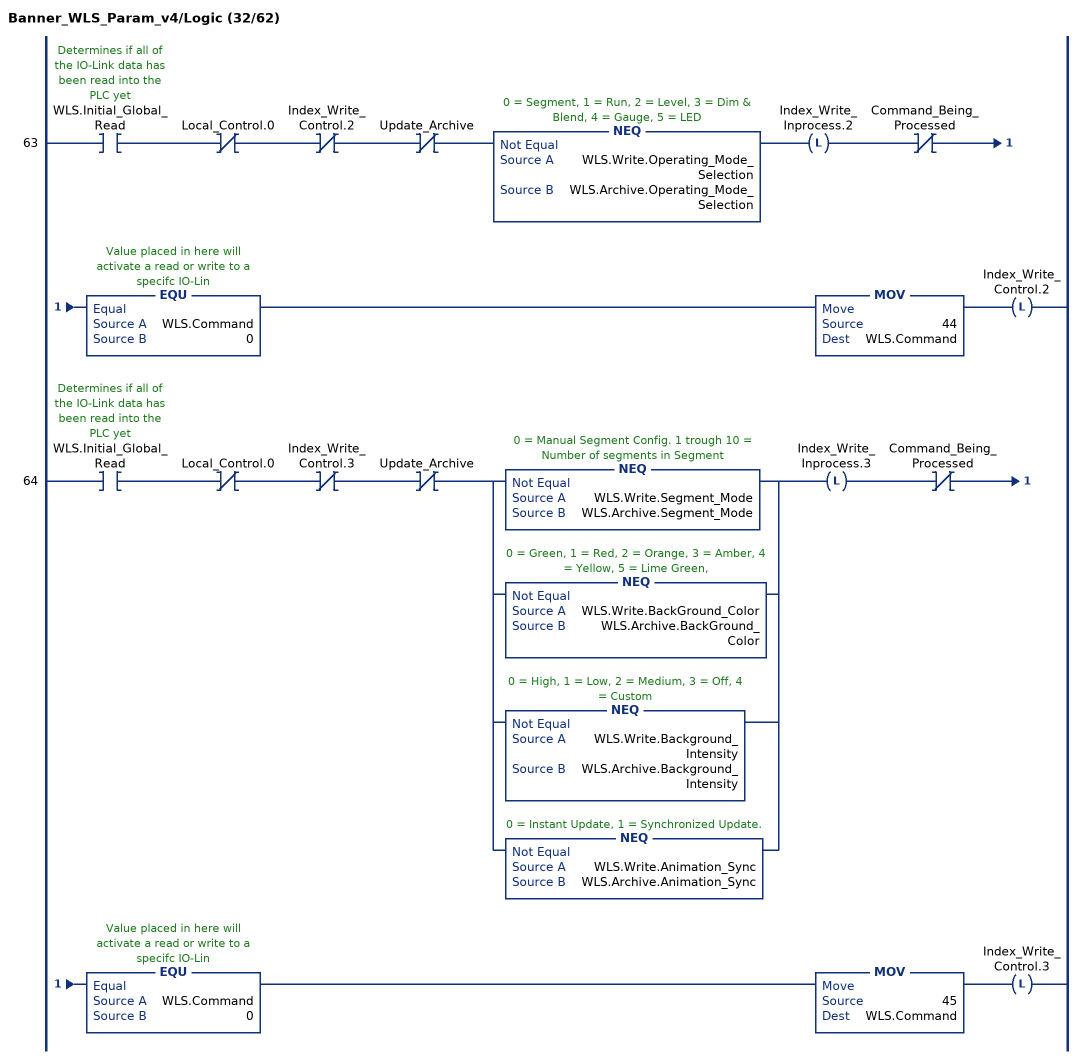
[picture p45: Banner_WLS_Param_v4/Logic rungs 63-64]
   63: XIC(WLS.Initial_Global_Read)XIO(Local_Control.0)XIO(Index_Write_Control.2)XIO(Update_Archive)NEQ(WLS.Write.Operating_Mode_Selection,WLS.Archive.Operating_Mode_Selection)OTL(Index_Write_Inprocess.2)XIO(Command_Being_Processed)EQU(WLS.Command,0)MOV(44,WLS.Command)OTL(Index_Write_Control.2);
   64: XIC(WLS.Initial_Global_Read)XIO(Local_Control.0)XIO(Index_Write_Control.3)XIO(Update_Archive)[NEQ(WLS.Write.Segment_Mode,WLS.Archive.Segment_Mode) ,NEQ(WLS.Write.BackGround_Color,WLS.Archive.BackGround_Color) ,NEQ(WLS.Write.Background_Intensity,WLS.Archive.Background_Intensity) ,NEQ(WLS.Write.Animation_Sync,WLS.Archive.Animation_Sync) ]OTL(Index_Write_Inprocess.3)XIO(Command_Being_Processed)EQU(WLS.Command,0)MOV(45,WLS.Command)OTL(Index_Write_Control.3);
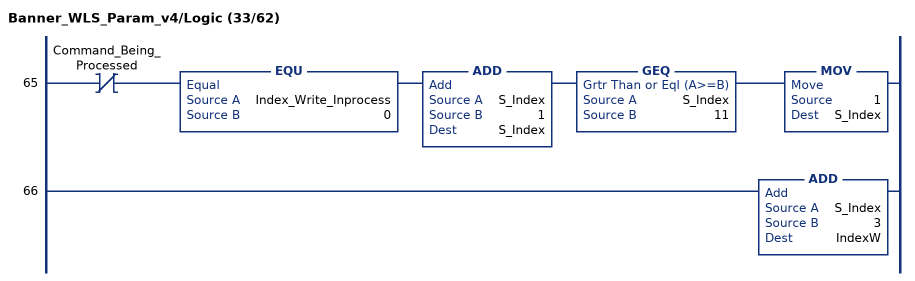
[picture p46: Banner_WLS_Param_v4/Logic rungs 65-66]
   65: XIO(Command_Being_Processed)EQU(Index_Write_Inprocess,0)ADD(S_Index,1,S_Index)GEQ(S_Index,11)MOV(1,S_Index);
   66: ADD(S_Index,3,IndexW);
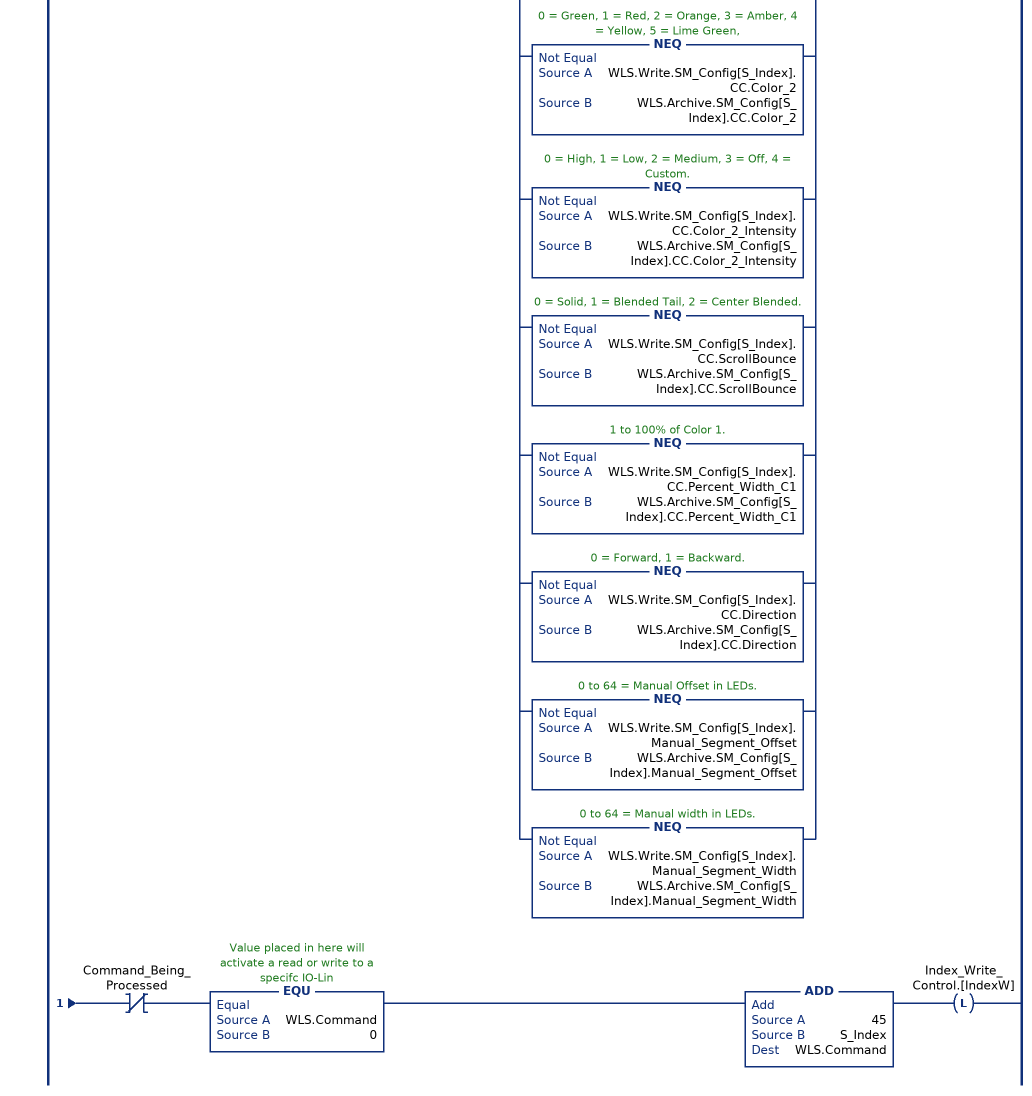
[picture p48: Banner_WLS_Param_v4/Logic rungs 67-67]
   67: XIC(WLS.Initial_Global_Read)XIO(Local_Control.0)XIO(Index_Write_Control.[IndexW])XIO(Update_Archive)[NEQ(WLS.Write.SM_Config[S_Index].Basic_Color,WLS.Archive.SM_Config[S_Index].Basic_Color) ,NEQ(WLS.Write.SM_Config[S_Index].Basic_Flash_Rate,WLS.Archive.SM_Config[S_Index].Basic_Flash_Rate) ,NEQ(WLS.Write.SM_Config[S_Index].CC.Animation,WLS.Archive.SM_Config[S_Index].CC.Animation) ,NEQ(WLS.Write.SM_Config[S_Index].CC.Color_1,WLS.Archive.SM_Config[S_Index].CC.Color_1) ,NEQ(WLS.Write.SM_Config[S_Index].CC.Color_1_Intensity,WLS.Archive.SM_Config[S_Index].CC.Color_1_Intensity) ,NEQ(WLS.Write.SM_Config[S_Index].CC.Speed,WLS.Archive.SM_Config[S_Index].CC.Speed) ,NEQ(WLS.Write.SM_Config[S_Index].CC.Pulse_Pattern,WLS.Archive.SM_Config[S_Index].CC.Pulse_Pattern) ,NEQ(WLS.Write.SM_Config[S_Index].CC.Color_2,WLS.Archive.SM_Config[S_Index].CC.Color_2) ,NEQ(WLS.Write.SM_Config[S_Index].CC.Color_2_Intensity,WLS.Archive.SM_Config[S_Index].CC.Color_2_Intensity) ,NEQ(WLS.Write.SM_Config[S_Index].CC.ScrollBounce,WLS.Archive.SM_Config[S_Index].CC.ScrollBounce) ,NEQ(WLS.Write.SM_Config[S_Index].CC.Percent_Width_C1,WLS.Archive.SM_Config[S_Index].CC.Percent_Width_C1) ,NEQ(WLS.Write.SM_Config[S_Index].CC.Direction,WLS.Archive.SM_Config[S_Index].CC.Direction) ,NEQ(WLS.Write.SM_Config[S_Index].Manual_Segment_Offset,WLS.Archive.SM_Config[S_Index].Manual_Segment_Offset) ,NEQ(WLS.Write.SM_Config[S_Index].Manual_Segment_Width,WLS.Archive.SM_Config[S_Index].Manual_Segment_Width) ]OTL(Index_Write_Inprocess.[IndexW])XIO(Command_Being_Processed)EQU(WLS.Command,0)ADD(45,S_Index,WLS.Command)OTL(Index_Write_Control.[IndexW]);
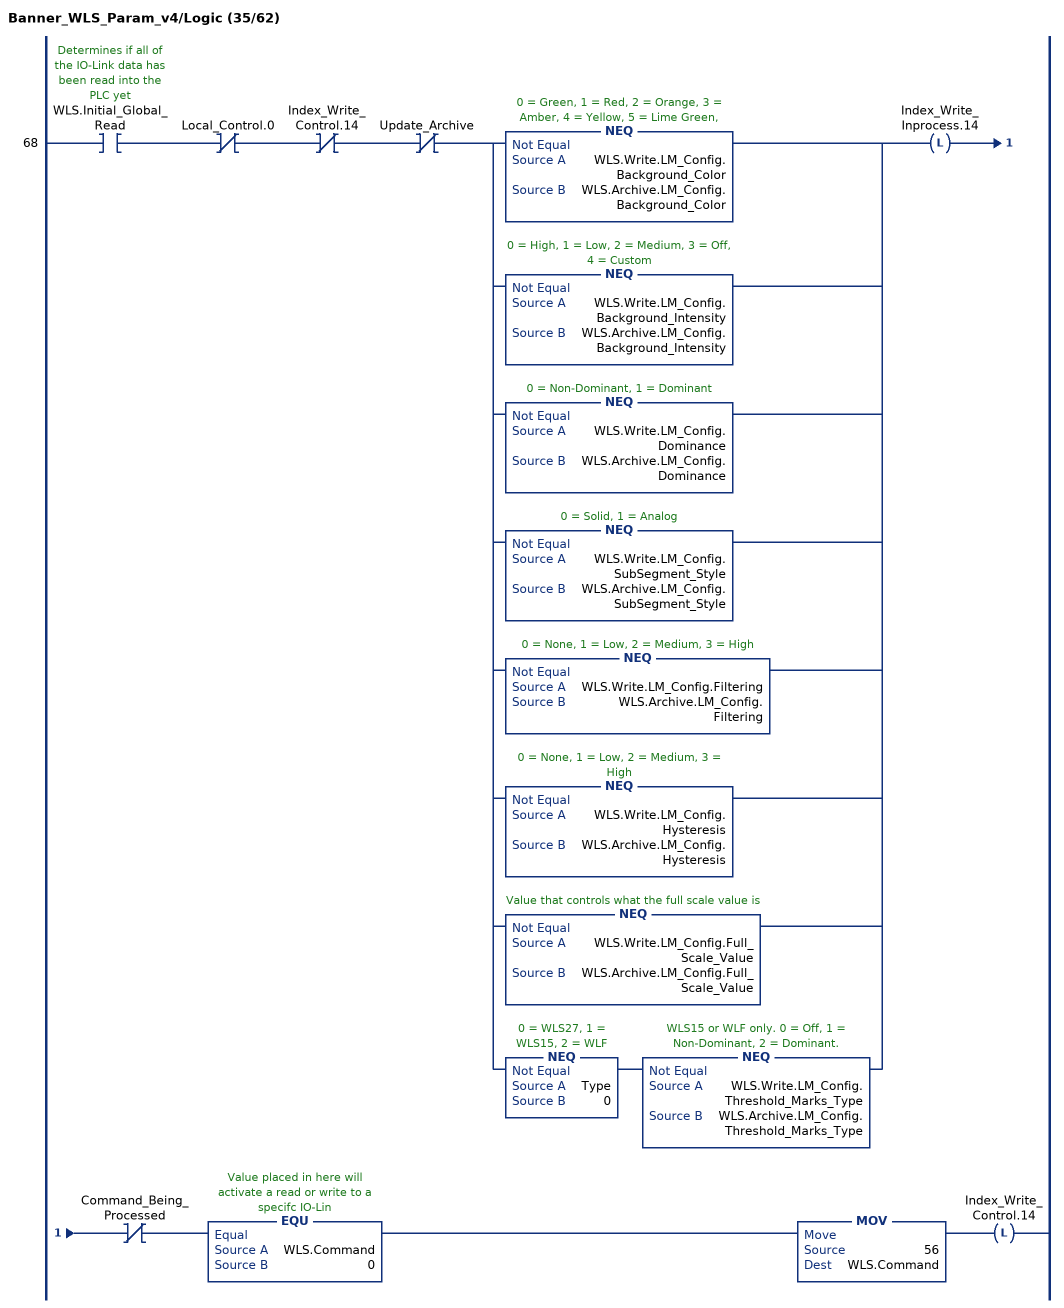
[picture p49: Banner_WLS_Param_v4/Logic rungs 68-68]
   68: XIC(WLS.Initial_Global_Read)XIO(Local_Control.0)XIO(Index_Write_Control.14)XIO(Update_Archive)[NEQ(WLS.Write.LM_Config.Background_Color,WLS.Archive.LM_Config.Background_Color) ,NEQ(WLS.Write.LM_Config.Background_Intensity,WLS.Archive.LM_Config.Background_Intensity) ,NEQ(WLS.Write.LM_Config.Dominance,WLS.Archive.LM_Config.Dominance) ,NEQ(WLS.Write.LM_Config.SubSegment_Style,WLS.Archive.LM_Config.SubSegment_Style) ,NEQ(WLS.Write.LM_Config.Filtering,WLS.Archive.LM_Config.Filtering) ,NEQ(WLS.Write.LM_Config.Hysteresis,WLS.Archive.LM_Config.Hysteresis) ,NEQ(WLS.Write.LM_Config.Full_Scale_Value,WLS.Archive.LM_Config.Full_Scale_Value) ,NEQ(Type,0) NEQ(WLS.Write.LM_Config.Threshold_Marks_Type,WLS.Archive.LM_Config.Threshold_Marks_Type) ]OTL(Index_Write_Inprocess.14)XIO(Command_Being_Processed)EQU(WLS.Command,0)MOV(56,WLS.Command)OTL(Index_Write_Control.14);
